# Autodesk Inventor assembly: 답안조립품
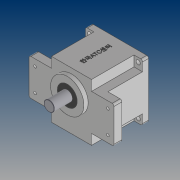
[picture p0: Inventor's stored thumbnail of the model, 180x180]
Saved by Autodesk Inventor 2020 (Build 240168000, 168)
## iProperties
Created: 2020-07
Part Number: 답안조립품
Document SubType Name: Assembly
Designer: PC312-
Author: PC312-
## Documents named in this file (10)
- C:\Users\PC312-\Desktop\700718V1006\답안조립품.iam
- C:\Users\PC312-\Desktop\700718V1006\본체.ipt
- C:\Users\PC312-\Desktop\700718V1006\베어링 608.ipt
- C:\Users\PC312-\Desktop\700718V1006\커버.ipt
- C:\Users\PC312-\Desktop\700718V1006\오일 실 8 22 7.ipt
- C:\Users\PC312-\Desktop\700718V1006\오일 실 17 32 8.ipt
- C:\Users\PC312-\Desktop\700718V1006\베어링 6003.ipt
- C:\Users\PC312-\Desktop\700718V1006\메인 축.ipt
- C:\Users\PC312-\Desktop\700718V1006\서브 축.ipt
- C:\Users\PC312-\Desktop\700718V1006\볼트 M4.ipt
